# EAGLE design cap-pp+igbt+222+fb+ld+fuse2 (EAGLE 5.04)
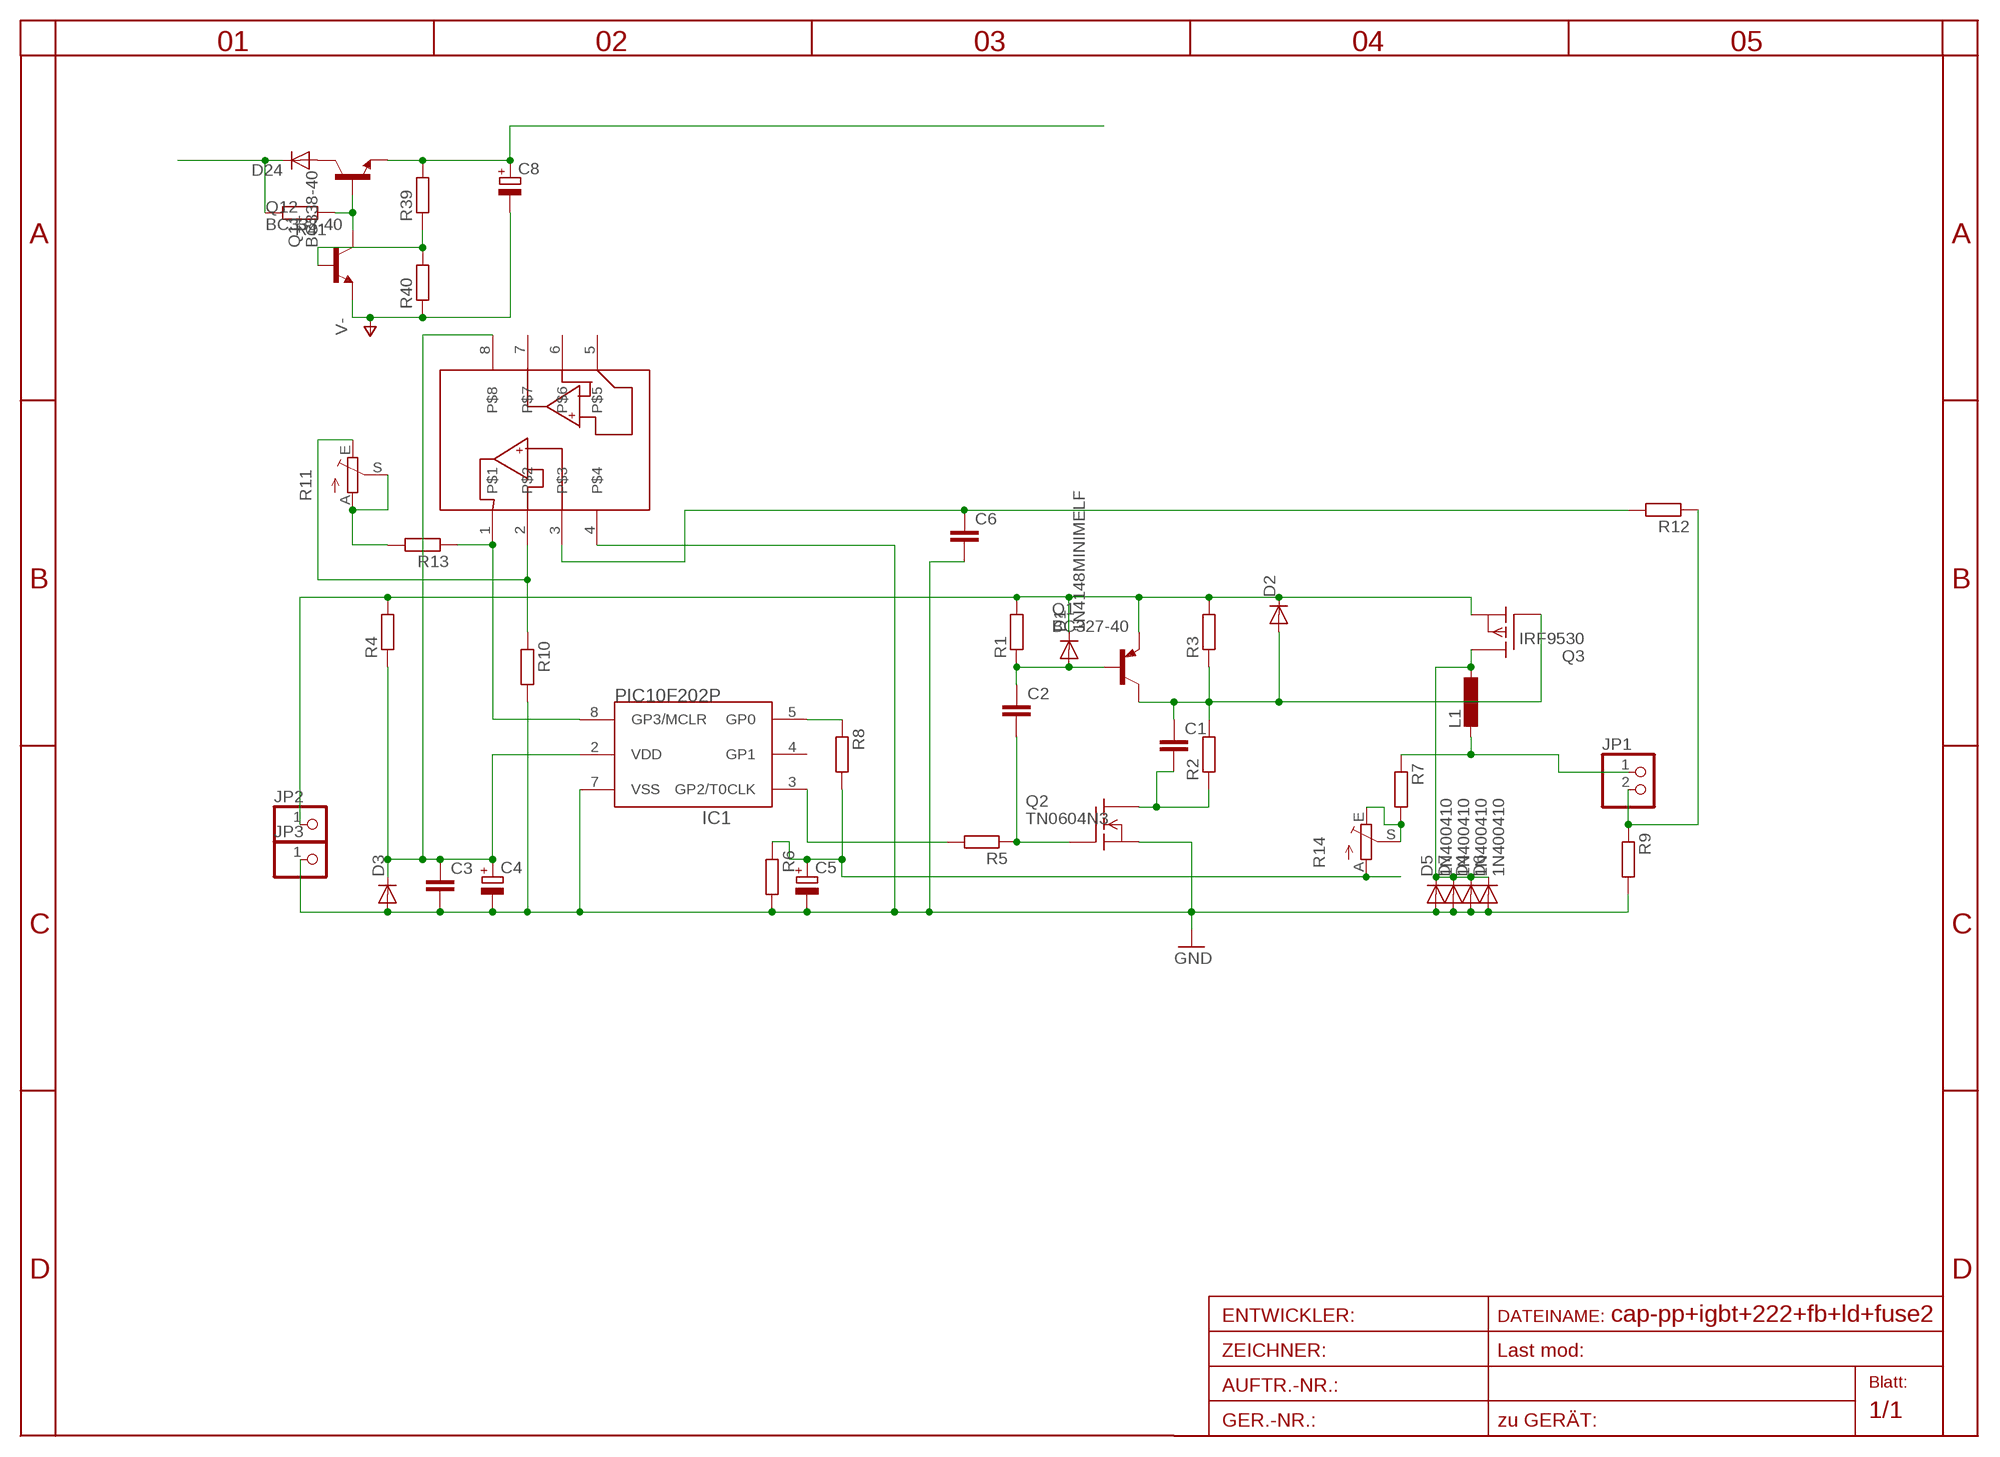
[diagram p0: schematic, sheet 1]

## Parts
C1  C-EU025_050-025X075  [C025_050-025X075]
C2  C-EU025_050-025X075  [C025_050-025X075]
C3  C-EU025_050-025X075  [C025_050-025X075]
C4  CPOL-EU5-13  [2,5-5-FLAT]
C5  CPOL-EU5-13  [2,5-5-FLAT]
C6  C-EU025_050-025X075  [C025_050-025X075]
C8  CPOL-EU5-13  [2,5-5-FLAT]
D1  1N4148MINIMELF  [MINIMELF]
D2  DIODE-D-5  [D-5]
D3  DIODE-D-2.5  [D-2.5]
D4  1N400410  [DO41-10]
D5  1N400410  [DO41-10]
D6  1N400410  [DO41-10]
D7  1N400410  [DO41-10]
D24  DIODE-D-7.5  [D-7.5]
IC1  PIC10F202P  [DIL8]
JP1  PINHD-1X2  [1X02]
JP2  PINHD-1X1  [1X01]
JP3  PINHD-1X1  [1X01]
L1  L-EU0204/7  [0204/7]
Q1  BC327-40  [TO92-EBC]
Q2  TN0604N3  [TO-92]
Q3  IRF9530  [TO220]
Q11  BC338-40  [TO92-EBC]
Q12  BC338-40  [TO92-EBC]
R1  R-EU_0204/2V  [0204V]
R2  R-EU_0204/2V  [0204V]
R3  R-EU_0204/2V  [0204V]
R4  R-EU_0204/2V  [0204V]
R5  R-EU_0204/2V  [0204V]
R6  R-EU_0204/2V  [0204V]
R7  R-EU_0204/2V  [0204V]
R8  R-EU_0204/2V  [0204V]
R9  R-EU_0207/15  [0207/15]
R10  R-EU_0204/7  [0204/7]
R11  TRIM_EU-CIP20C-4MM  [CIP20C-4MM]
R12  R-EU_0204/2V  [0204V]
R13  R-EU_0204/2V  [0204V]
R14  TRIM_EU-CIP20C-4MM  [CIP20C-4MM]
R39  R-EU_0207/10  [0207/10]
R40  R-EU_0204/2V  [0204V]
R41  R-EU_0207/10  [0207/10]
U$1  MCP6042SOIC  [SO-08]

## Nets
BB: C2.2 Q2.2(G) R5.1
DRAIN: D4.C D5.C D6.C D7.C L1.1 Q3.2(D)
GND: C3.2 C4.- C5.- C6.2 D3.A D4.A D5.A D6.A D7.A IC1.7(VSS) JP3.1 Q2.1(S) R6.2 R9.2 R10.2 U$1.4
MPOINT: C5.+ R6.1 R8.2 R14.A
N$1: C1.2 Q2.3(D) R2.1
N$2: C8.+ Q11.E R39.2
N$3: IC1.3(GP2/T0CLK) R5.2
N$4: C3.1 C4.+ D3.C IC1.2(VDD) R4.1 U$1.8
N$5: IC1.5(GP0) R8.1
N$6: R10.1 R11.E U$1.2
N$7: IC1.8(GP3/MCLR) R13.1 U$1.1
N$8: C6.1 R12.2 U$1.3
N$9: R11.A R11.S R13.2
N$10: R7.2 R14.E R14.S
N$36: D24.A Q11.C
N$38: Q11.B Q12.C R41.1
N$41: Q12.B R39.1 R40.2
OUT: C1.1 D2.A Q1.C Q3.1(G) R2.2 R3.1
OUT+: JP1.1 L1.2 R7.1
OUT-: JP1.2 R9.1 R12.1
TB: C2.1 D1.A Q1.B R1.1
V+: D1.C D2.C JP2.1 Q1.E Q3.3(S) R1.2 R3.2 R4.2
V-: C8.- Q12.E R40.1
VIN: D24.C R41.2
Unconnected: IC1.4(GP1) U$1.5 U$1.6 U$1.7

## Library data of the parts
C1-C3 C6 = rcl-2:C-EU: CAPACITOR, European symbol
C4 C5 C8 = rcl-2:CPOL-EU: POLARIZED CAPACITOR, European symbol
D1 = diode-1:1N4148: DIODE
D2 D3 D24 = diode-1:DIODE-: DIODE
D4-D7 = diode-1:1N4004: DIODE
IC1 = microchip-5:PIC10F20*: uPC nW 0,25/0,5k Program Flash memory
JP1 = pinhead:PINHD-1X2: PIN HEADER
JP2 JP3 = pinhead:PINHD-1X1: PIN HEADER
L1 = rcl-2:L-EU: INDUCTOR, European symbol
Q1 = transistor-pnp:BC327*: PNP Transistror
Q2 = transistor-fet:TN0604N3: N-Channel Enhancement MOSFET 40V; 4A; 0,75Ohm
Q3 = transistor-fet:IRF9530: P-Channel Enhancement MOSFET (HEXFET); -100V; -12A; 0,3Ohm
Q11 Q12 = transistor-npn:BC338*: NPN Transistor
R1-R10 R12 R13 R39-R41 = rcl-2:R-EU_: RESISTOR, European symbol
R11 R14 = pot:TRIM_EU-: POTENTIOMETER
U$1 = microchip-3:MCP6042

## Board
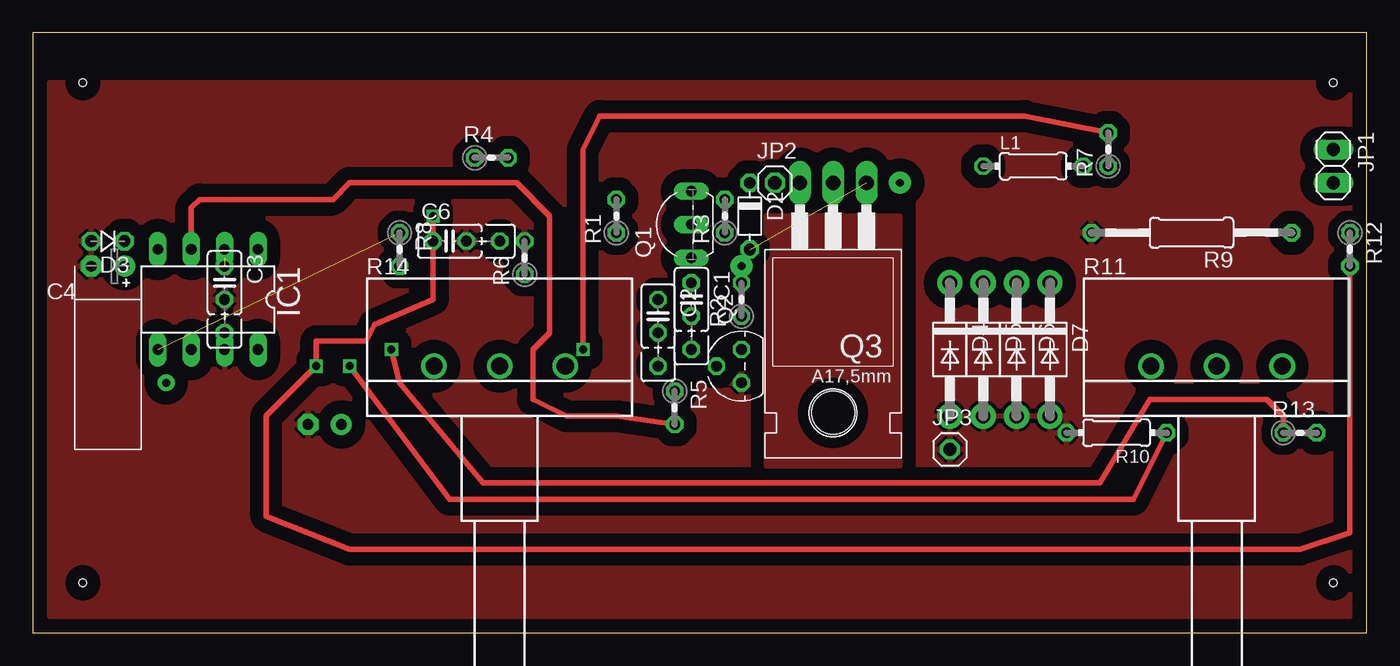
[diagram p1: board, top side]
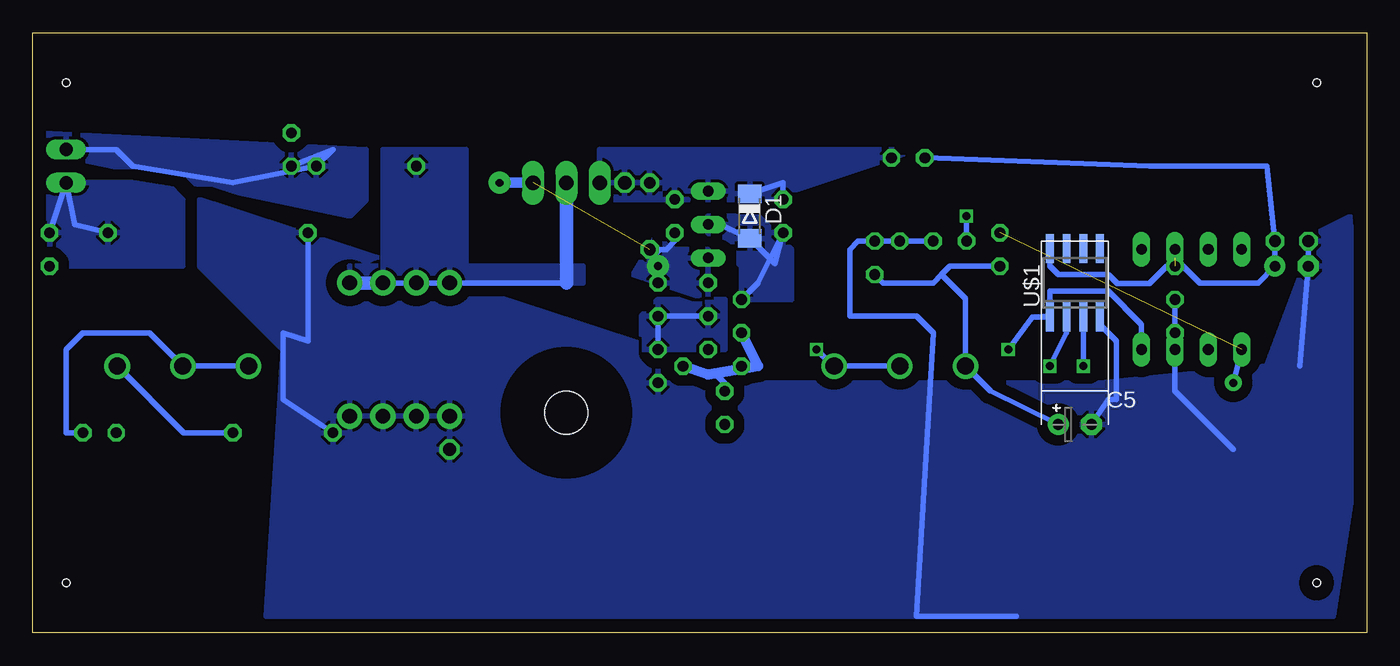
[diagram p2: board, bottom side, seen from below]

Size 101.6 x 45.72 mm. Coordinates in mm from the lower left corner, seen from the top.
Outline: 0,0 101.6,0 101.6,45.72 0,45.72 0,0
Copper layers (1*16): Top 0.035mm / dielectric 1.5mm / Bottom 0.035mm
Design rules "default": minimum track width 10mil, minimum drill 24mil, track to track 8mil, track to pad 8mil, pad to pad 8mil, via to via 8mil, smd to smd 8mil, copper to edge 40mil, drill to drill 8mil, minimum pad ring 10mil, minimum via ring 8mil, stop-mask expansion 4mil, vias tented up to drill 0mil, thermal gap 10mil
Holes 0.6 mm at 3.81,41.91 3.81,3.81 99.06,3.81 99.06,41.91

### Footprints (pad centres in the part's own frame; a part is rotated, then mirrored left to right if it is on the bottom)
C025_050-025X075 = drill 0.813 octagon: 1 -1.27,0; 2 1.27,0; 3 3.81,0
2,5-5-FLAT = drill 0.813 pad 1.6 round: + -1.27,0 | drill 0.813 pad 1.6 octagon: - 1.27,0
MINIMELF = smd 1.4 x 1.8: A 1.7,0; C -1.7,0
D-5 = drill 0.9 octagon: A 2.54,0; C -2.54,0
D-2.5 = drill 0.9 octagon: A 1.27,0; C -1.27,0
DO41-10 = drill 1.118 pad 1.93 round: A 5.08,0; C -5.08,0
D-7.5 = drill 0.813 long: A 3.81,0; C -3.81,0
DIL8 = drill 0.813 long: 1 -3.81,-3.81; 2 -1.27,-3.81; 3 1.27,-3.81; 4 3.81,-3.81; 5 3.81,3.81; 6 1.27,3.81; 7 -1.27,3.81; 8 -3.81,3.81
1X02 = drill 1.016 long: 1 -1.27,0; 2 1.27,0
1X01 = drill 1.016 octagon: 1 0,0
0204/7 = drill 0.813 octagon: 1 -3.81,0; 2 3.81,0
TO92-EBC = drill 0.813 long: B 0,-1.27; C -2.54,-1.27; E 2.54,-1.27
TO-92 = drill 0.813 octagon: 1 -1.27,0; 2 0,1.905; 3 1.27,0
TO220 = drill 1.118 long: 1 -2.54,-6.35; 2 0,-6.35; 3 2.54,-6.35 | hole 3.302: 0,11.176
0204V = drill 0.813 octagon: 1 -1.27,0; 2 1.27,0
0207/15 = drill 0.813 octagon: 1 -7.62,0; 2 7.62,0
CIP20C-4MM = drill 1.3 pad 1.93 round: A -5,0; E 5,0; S 0,0
0207/10 = drill 0.813 octagon: 1 -5.08,0; 2 5.08,0
SO-08 = smd 0.6 x 2.2: 1 -1.905,-2.6; 2 -0.635,-2.6; 3 0.635,-2.6; 4 1.905,-2.6; 5 1.905,2.6; 6 0.635,2.6; 7 -0.635,2.6; 8 -1.905,2.6

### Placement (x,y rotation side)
C1  50.16,25.4 270 top
C2  47.62,24.13 270 top
C3  14.61,26.67 270 top
C4  5.71,27.94 180 top
C5  22.23,15.88 0 bottom
C6  31.75,29.84 0 top
C8  not placed on the board
D1  46.99,31.75 270 bottom
D2  54.61,31.75 270 top
D3  5.71,29.84 180 top
D4  69.85,21.59 270 top
D5  72.39,21.59 270 top
D6  74.93,21.59 270 top
D7  77.47,21.59 270 top
D24  not placed on the board
IC1  13.34,25.4 180 top
JP1  99.06,35.56 270 top
JP2  56.52,34.29 0 top
JP3  69.85,13.97 0 top
L1  76.2,35.56 0 top
Q1  48.9,31.11 90 top
Q2  53.98,20.32 90 top
Q3  60.96,27.94 180 top
Q11  not placed on the board
Q12  not placed on the board
R1  44.45,31.75 90 top
R2  53.98,25.4 90 top
R3  52.7,31.75 90 top
R4  34.92,36.2 0 top
R5  48.9,17.14 270 top
R6  37.47,28.57 90 top
R7  81.92,36.83 90 top
R8  27.94,29.21 270 top
R9  88.27,30.48 180 top
R10  82.55,15.24 180 top
R11  90.17,20.32 0 top
R12  100.33,29.21 270 top
R13  96.52,15.24 0 top
R14  35.56,20.32 0 top
R39  not placed on the board
R40  not placed on the board
R41  not placed on the board
U$1  22.23,26.67 0 bottom

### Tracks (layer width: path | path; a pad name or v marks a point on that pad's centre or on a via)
BB
  Bottom 0.406: R5.1 48.9,19.02 49.65,19.77
  Bottom 0.813: Q2.2 50.16,19.68 49.65,19.77 46.35,20.32 C2.2
DRAIN
  Bottom 0.406: Q3.2 60.96,35.56 | 60.96,26.67 D4.C D5.C D6.C
  Bottom 1.016: 60.96,26.67 Q3.2 | D6.C D7.C
  pour Bottom (isolate 0.61): 74.93,36.83 68.58,36.83 68.58,27.94 59.69,27.94 59.69,26.67 77.47,26.67 77.47,27.94 74.93,27.94
  pour Top (isolate 0.813, rank 4): 66.04,31.75 66.04,12.7 55.88,12.7 55.88,31.75
GND
  Bottom 0.406: D3.A C4.- 5.08,20.32 | 10.16,13.97 14.61,18.41 IC1.7 C3.2 | U$1.4 20.32,23.5 19.05,22.23 19.05,17.78 19.68,17.78 C5.- | R9.2 80.64,22.23 82.55,22.86 82.55,17.78 R10.2 | 26.67,1.27 34.29,1.27 33.02,22.86 34.29,24.13 39.37,24.13 39.37,29.21 38.73,29.84 R6.2 C6.2
  pour Bottom (isolate 0.813): 1.27,31.75 0,17.78 2.54,1.27 83.82,1.27 82.55,21.59 88.9,27.94 88.9,33.02 53.98,21.59 52.7,19.05 20.32,19.05 7.62,20.32 3.81,30.48
  pour Top (isolate 1.016, rank 5): 1.27,41.91 100.33,41.91 100.33,1.27 1.27,1.27
MPOINT
  Bottom 0.406: C5.+ 28.66,18.41 R14.A 30.56,25.48 32.38,27.3 | R8.2 31.75,27.94 32.38,27.3 | 32.38,27.3 33.02,26.67 36.83,26.67 R6.1
N$1
  Bottom 0.406: C1.2 R2.1 Q2.3
  pour Bottom (isolate 0.254, rank 3): 48.9,25.4 53.98,25.4 55.24,24.13 55.24,21.59 48.9,21.59
N$2  (2 unrouted)
N$3
  Top 0.406: IC1.3 12.06,32.38 12.7,33.02 22.86,33.02 24.13,34.29 36.83,34.29 39.37,31.75 39.37,22.86 38.1,21.59 38.1,17.78 40.64,16.51 44.45,16.51 R5.2
N$4  (1 unrouted)
  Bottom 0.406: C3.1 15.24,27.94 16.57,26.61 18.99,26.61 19.68,27.3 23.5,27.3 24.13,27.94 U$1.8 | R4.1 16.51,35.56 7.62,35.56 D3.C C4.+ 8.26,26.67 12.7,26.67 14.61,28.57 | C3.1 IC1.2 C3.1
N$5  (via drill 0.6 pad 1.27)  (1 unrouted)
  Bottom 0.406: IC1.5 v10.16,19.05
N$6  (via drill 0.6)
  Top 0.406: v24.13,20.32 31.75,10.16 83.82,10.16 R10.1
  Bottom 0.406: v24.13,20.32 22.86,22.86 U$1.2 | R10.1 90.09,15.24 R11.E
N$7  (via drill 0.6)
  Top 0.406: v27.3,21.59 27.94,19.05 34.29,11.43 81.28,11.43 85.09,17.78 93.98,17.78 95.25,16.51 R13.1
  Bottom 0.406: 25.46,24.07 U$1.1 | 25.46,24.07 v27.3,21.59 | 25.46,24.07 24.13,24.13 24.13,26.04 19.68,26.04 17.14,23.5 IC1.8
N$8  (via drill 0.6)
  Top 0.406: R12.2 100.33,7.62 96.52,6.35 24.13,6.35 17.78,8.89 17.78,16.51 v21.59,20.32 21.59,22.23 25.4,22.23 26.04,23.5 30.48,25.4 v30.48,31.75
  Bottom 0.406: v21.59,20.32 U$1.3 | v30.48,31.75 C6.1
N$9
  Bottom 0.406: R13.2 99.06,15.24 99.06,21.59 97.79,22.86 92.71,22.86 R11.S R11.A
N$10  (via drill 0.6)
  Top 0.406: v41.91,21.59 41.91,36.83 43.18,39.37 75.56,39.37 R7.2
  Bottom 0.406: R14.S R14.E 40.64,20.32 v41.91,21.59
N$36  (1 unrouted)
N$38  (2 unrouted)
N$41  (2 unrouted)
OUT  (via drill 0.6 pad 1.68)  (1 unrouted)
  Bottom 0.406: R3.1 52.7,29.84 53.34,29.21 53.85,29.21 54.36,28.7
  Bottom 0.813: Q3.1 v66.04,34.29 | D2.A 54.36,28.7 v53.98,27.94
  pour Bottom (isolate 0.813, rank 2): 50.16,29.21 52.7,29.21 53.98,30.48 55.88,27.3 50.16,25.4
OUT+
  Bottom 0.406: JP1.1 95.25,36.83 93.98,35.56 86.36,34.29 L1.2 78.74,36.83 R7.1
  pour Bottom (isolate 0.813, rank 2): 76.2,36.83 76.2,33.02 77.47,31.75 101.6,36.83 101.6,38.1
OUT-
  Bottom 0.406: R9.1 98.42,31.11 JP1.2 R12.1
  pour Bottom (isolate 0.813): 90.17,33.02 90.17,27.94 99.06,27.94 101.6,30.48 101.6,34.29 91.44,34.29
TB
  Bottom 0.406: C2.1 46.35,26.67 R1.1 45.09,28.14 D1.A 49.73,31.32 49.96,31.32 Q1.B
  pour Bottom (isolate 0.813, rank 3): 47.62,25.4 43.81,25.4 43.81,29.21 46.35,31.75 50.16,31.75 50.16,30.48 47.62,27.94
V+
  Bottom 0.406: R1.2 44.45,34.29 D1.C
  pour Bottom (isolate 0.813, rank 2): 34.29,36.83 58.42,36.83 58.42,33.02 45.72,33.02
V-  (2 unrouted)
VIN  (1 unrouted)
